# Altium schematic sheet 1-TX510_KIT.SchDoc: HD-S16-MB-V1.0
size A4
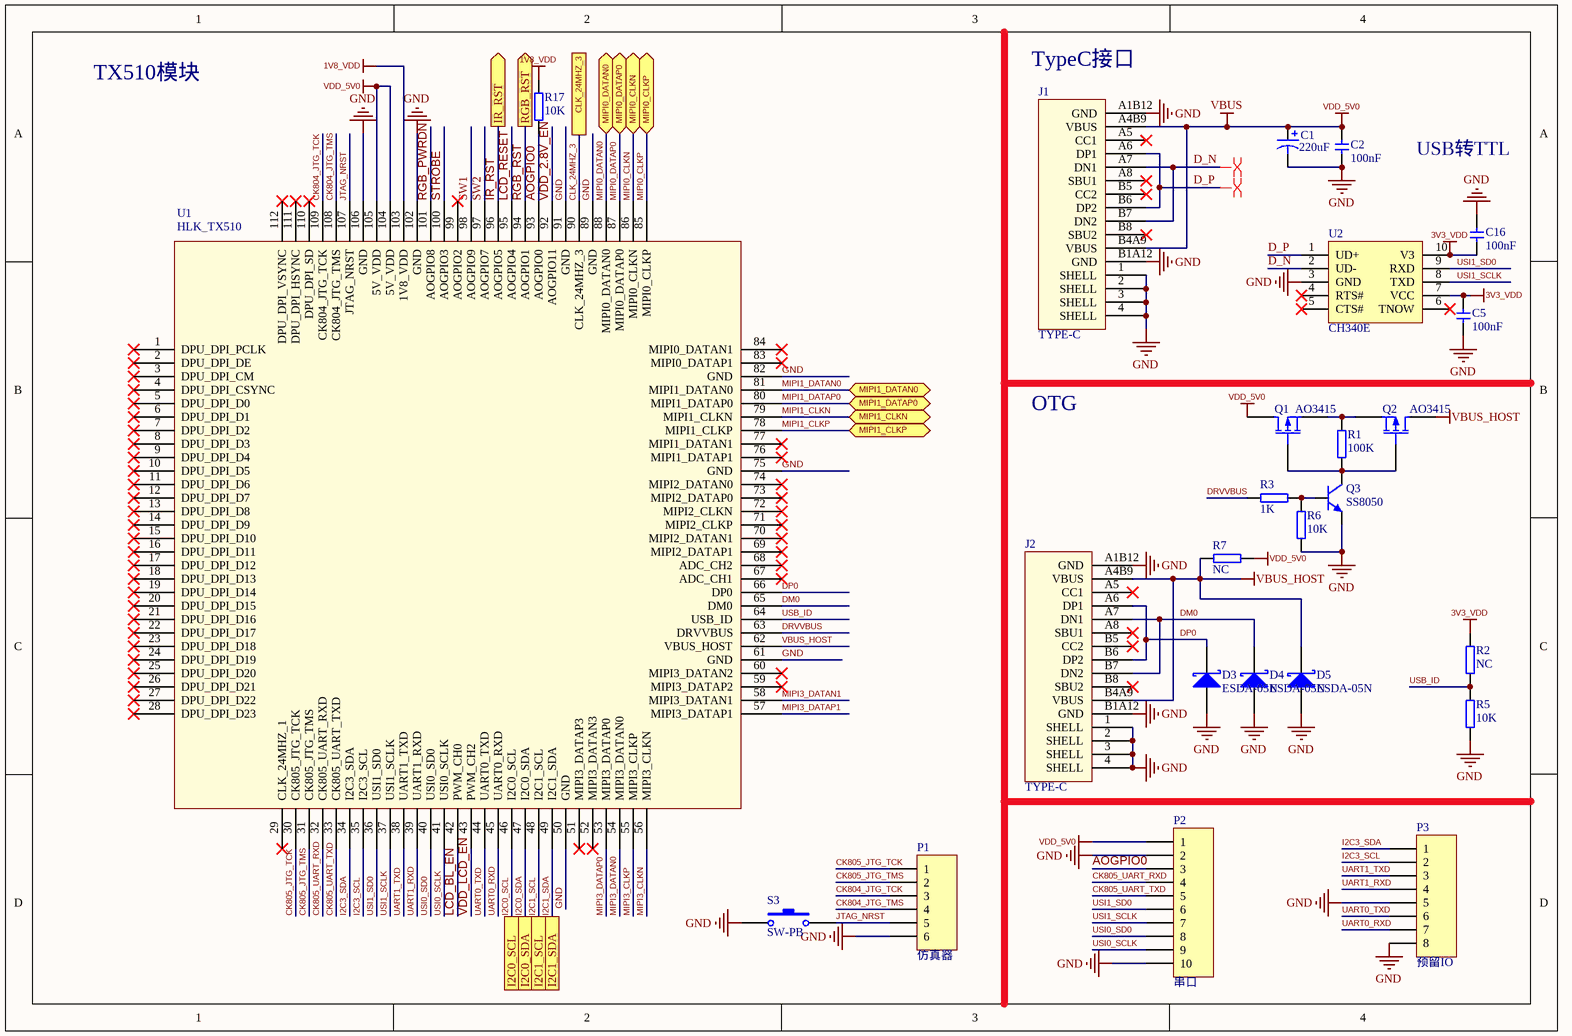
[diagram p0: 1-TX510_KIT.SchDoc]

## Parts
C1  value 220uF  [SMD,6.3x7.7mm]  (hidden comment: Cap Pol1)
C2  100nF  [C0402]
C5  100nF  [C0402]
C16  100nF  [C0402]
D3  ESDA-05N  [R0402]
D4  ESDA-05N  [R0402]
D5  ESDA-05N  [R0402]
J1  TYPE-C  [TYPE-C16PIN]
J2  TYPE-C  [TYPE-C16PIN]
P1  仿真器  [HDR1X6]
P2  串口  [HDR1X10]
P3  预留IO  [HDR1X8]
Q1  AO3415  [SOT-23]
Q2  AO3415  [SOT-23]
Q3  SS8050  [SOT23-BEC]
R1  100K  [R0402]
R2  NC  [R0402]
R3  1K  [R0402]
R5  10K  [R0402]
R6  10K  [R0402]
R7  NC  [RES_0603]
R17  10K  [R0402]
S3  SW-PB  [轻触开关4.5x4.5]
U1  HLK_TX510  [HLK_TX510 _KIT]
U2  CH340E  [MSOP-10]

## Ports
CLK_24MHZ_3, I2C0_SCL, I2C0_SDA, I2C1_SCL, I2C1_SDA, IR_RST (out), MIPI0_CLKN (bidir), MIPI0_CLKP (bidir), MIPI0_DATAN0 (bidir), MIPI0_DATAP0 (bidir), MIPI1_CLKN (bidir), MIPI1_CLKP (bidir), MIPI1_DATAN0 (bidir), MIPI1_DATAP0 (bidir), RGB_RST (out)

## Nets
1V8_VDD: R17.2 U1.103(1V8_VDD)
3V3_VDD: C5.2 C16.1 R2.2 U2.7(VCC) U2.10(V3)
GND: C1.2 C2.1 C5.1 C16.2 D3.1(A) D4.1(A) D5.1(A) J1.1(SHELL) J1.2(SHELL) J1.3(SHELL) J1.4(SHELL) J1.A1B12(GND) J1.B1A12(GND) J2.1(SHELL) J2.2(SHELL) J2.3(SHELL) J2.4(SHELL) J2.A1B12(GND) J2.B1A12(GND) P1.6 P2.2 P2.10 P3.5 P3.8 Q3.E R5.1 R6.1 S3.1 U1.50(GND) U1.61(GND) U1.75(GND) U1.82(GND) U1.89(GND) U1.91(GND) U1.102(GND) U1.106(GND) U2.3(GND)
VBUS: C1.1 C2.2 J1.A4B9(VBUS) J1.B4A9(VBUS) P2.1 Q1.3(D) R7.1 U1.104(5V_VDD) U1.105(5V_VDD)  [also labelled VDD_5V0]
VBUS_HOST: D5.2(K) J2.A4B9(VBUS) J2.B4A9(VBUS) Q2.3(D) R7.2 U1.62(VBUS_HOST)
AOGPIO0: P2.3 R17.1 U1.93(AOGPIO0)
CK804_JTG_TCK: P1.3 U1.109(CK804_JTG_TCK)
CK804_JTG_TMS: P1.4 U1.108(CK804_JTG_TMS)
CK805_JTG_TCK: P1.1 U1.30(CK805_JTG_TCK)
CK805_JTG_TMS: P1.2 U1.31(CK805_JTG_TMS)
CK805_UART_RXD: P2.4 U1.32(CK805_UART_RXD)
CK805_UART_TXD: P2.5 U1.33(CK805_UART_TXD)
CLK_24MHZ_3: U1.90(CLK_24MHZ_3) ; port CLK_24MHZ_3
D_N: J1.A7(DN1) J1.B7(DN2) U2.2(UD-)
D_P: J1.A6(DP1) J1.B6(DP2) U2.1(UD+)
DM0: D4.2(K) J2.A7(DN1) J2.B7(DN2) U1.65(DM0)
DP0: D3.2(K) J2.A6(DP1) J2.B6(DP2) U1.66(DP0)
DRVVBUS: R3.2 U1.63(DRVVBUS)
I2C0_SCL: U1.46(I2C0_SCL) ; port I2C0_SCL
I2C0_SDA: U1.47(I2C0_SDA) ; port I2C0_SDA
I2C1_SCL: U1.48(I2C1_SCL) ; port I2C1_SCL
I2C1_SDA: U1.49(I2C1_SDA) ; port I2C1_SDA
I2C3_SCL: P3.2 U1.35(I2C3_SCL)
I2C3_SDA: P3.1 U1.34(I2C3_SDA)
IR_RST: U1.96(AOGPIO5) ; port IR_RST
JTAG_NRST: P1.5 S3.2 U1.107(JTAG_NRST)
LCD_BL_EN: U1.42(PWM_CH0)
LCD_RESET: U1.95(AOGPIO4)
MIPI0_CLKN: U1.86(MIPI0_CLKN) ; port MIPI0_CLKN
MIPI0_CLKP: U1.85(MIPI0_CLKP) ; port MIPI0_CLKP
MIPI0_DATAN0: U1.88(MIPI0_DATAN0) ; port MIPI0_DATAN0
MIPI0_DATAP0: U1.87(MIPI0_DATAP0) ; port MIPI0_DATAP0
MIPI1_CLKN: U1.79(MIPI1_CLKN) ; port MIPI1_CLKN
MIPI1_CLKP: U1.78(MIPI1_CLKP) ; port MIPI1_CLKP
MIPI1_DATAN0: U1.81(MIPI1_DATAN0) ; port MIPI1_DATAN0
MIPI1_DATAP0: U1.80(MIPI1_DATAP0) ; port MIPI1_DATAP0
MIPI3_CLKN: U1.56(MIPI3_CLKN)
MIPI3_CLKP: U1.55(MIPI3_CLKP)
MIPI3_DATAN0: U1.54(MIPI3_DATAN0)
MIPI3_DATAN1: U1.58(MIPI3_DATAN1)
MIPI3_DATAP0: U1.53(MIPI3_DATAP0)
MIPI3_DATAP1: U1.57(MIPI3_DATAP1)
RGB_PWRDN: U1.101(AOGPIO8)
RGB_RST: U1.94(AOGPIO1) ; port RGB_RST
STROBE: U1.100(AOGPIO3)
SW1: U1.98(AOGPIO9)
SW2: U1.97(AOGPIO7)
UART0_RXD: P3.7 U1.45(UART0_RXD)
UART0_TXD: P3.6 U1.44(UART0_TXD)
UART1_RXD: P3.4 U1.39(UART1_RXD)
UART1_TXD: P3.3 U1.38(UART1_TXD)
USB_ID: R2.1 R5.2 U1.64(USB_ID)
USI0_SCLK: P2.9 U1.41(USI0_SCLK)
USI0_SD0: P2.8 U1.40(USI0_SD0)
USI1_SCLK: P2.7 U1.37(USI1_SCLK) U2.8(TXD)
USI1_SD0: P2.6 U1.36(USI1_SD0) U2.9(RXD)
VDD_2.8V_EN: U1.92(AOGPIO11)
VDD_LCD_EN: U1.43(PWM_CH2)
NetQ1_1: Q1.1(G) Q2.1(G) Q3.C R1.1
NetQ1_2: Q1.2(S) Q2.2(S) R1.2
NetQ3_B: Q3.B R3.1 R6.2

Not connected (* = marked no-connect by the designer): J1 A5(CC1)* A8(SBU1)* B5(CC2)* B8(SBU2)*; J2 A5(CC1)* A8(SBU1)* B5(CC2)* B8(SBU2)*; U1 1(DPU_DPI_PCLK)* 2(DPU_DPI_DE)* 3(DPU_DPI_CM)* 4(DPU_DPI_CSYNC)* 5(DPU_DPI_D0)* 6(DPU_DPI_D1)* 7(DPU_DPI_D2)* 8(DPU_DPI_D3)* 9(DPU_DPI_D4)* 10(DPU_DPI_D5)* 11(DPU_DPI_D6)* 12(DPU_DPI_D7)* 13(DPU_DPI_D8)* 14(DPU_DPI_D9)* 15(DPU_DPI_D10)* 16(DPU_DPI_D11)* 17(DPU_DPI_D12)* 18(DPU_DPI_D13)* 19(DPU_DPI_D14)* 20(DPU_DPI_D15)* 21(DPU_DPI_D16)* 22(DPU_DPI_D17)* 23(DPU_DPI_D18)* 24(DPU_DPI_D19)* 25(DPU_DPI_D20)* 26(DPU_DPI_D21)* 27(DPU_DPI_D22)* 28(DPU_DPI_D23)* 29(CLK_24MHZ_1)* 51(MIPI3_DATAP3)* 52(MIPI3_DATAN3)* 59(MIPI3_DATAP2)* 60(MIPI3_DATAN2)* 67(ADC_CH1)* 68(ADC_CH2)* 69(MIPI2_DATAP1)* 70(MIPI2_DATAN1)* 71(MIPI2_CLKP)* 72(MIPI2_CLKN)* 73(MIPI2_DATAP0)* 74(MIPI2_DATAN0)* 76(MIPI1_DATAP1)* 77(MIPI1_DATAN1)* 83(MIPI0_DATAP1)* 84(MIPI0_DATAN1)* 99(AOGPIO2)* 110(DPU_DPI_SD)* 111(DPU_DPI_HSYNC)* 112(DPU_DPI_VSYNC)*; U2 4(RTS#)* 5(CTS#)* 6(TNOW)*

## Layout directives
differential pair: D_N, D_P

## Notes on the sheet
- TX510模块
- (near J1) TypeC接口
- USB转TTL
- OTG

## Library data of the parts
C1 = Cap Pol1: Polarized Capacitor (Radial)
C2 C5 C16 = CAP1: C?
D3-D5 = Diode BAS70: Silicon AF Schottky Diode for High-Speed Switching; Note: Pin 2 is not connected and not drawn.
J1 J2 = TYPE-C16PIN
P1 = Header 6: Header, 6-Pin
P2 = Header 10: Header, 10-Pin
P3 = Header 8: Header, 8-Pin
Q3 = NPN: 贴片三极管
R1-R3 R5-R7 R17 = RES1: R?
S3 = SW-PB: Switch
